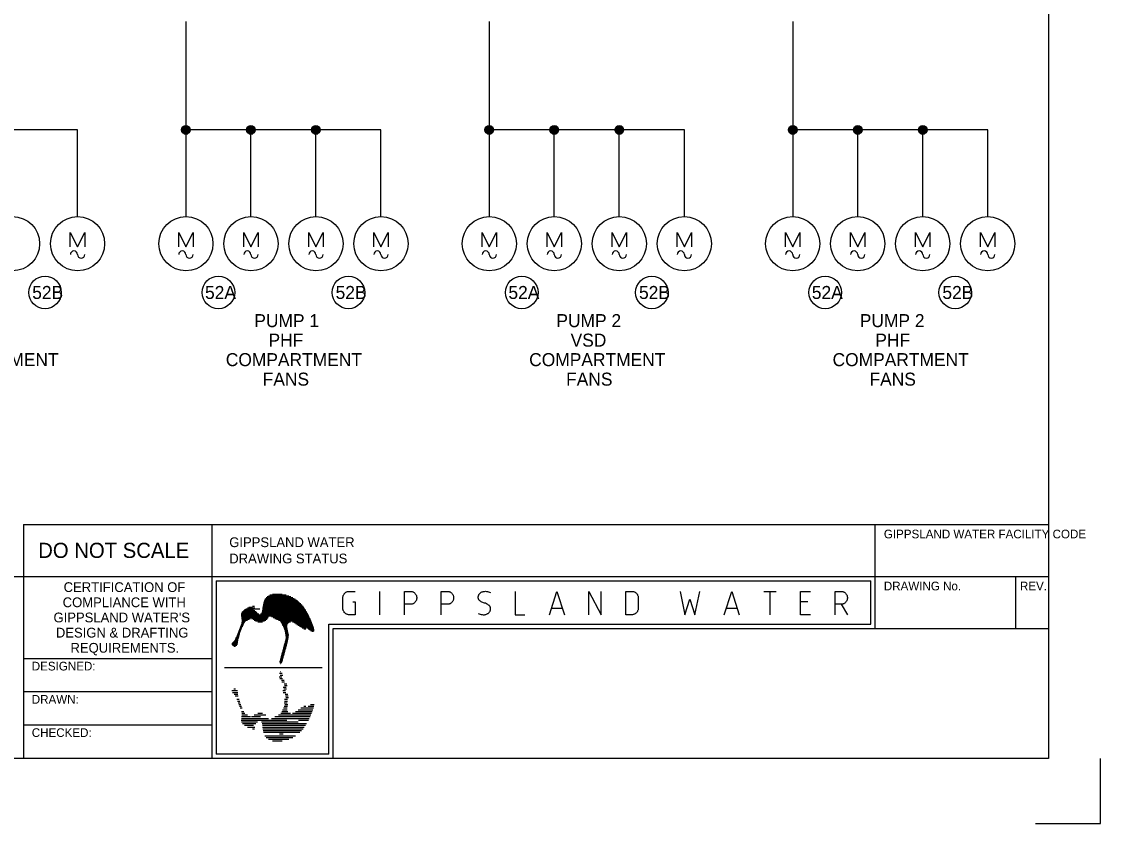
# Model space of a CAD drawing. Extents: x 0 to 841, y 0 to 594.
# Drawn here: x 592.1 to 841, y 0 to 185 of the extents above; entities that cross this region are included whole.
import ezdxf

# ---------------------------------------------------------------- set-up
doc = ezdxf.new("R2010")
doc.units = 0
for name, color, linetype in [('A1BORDER', 7, 'Continuous'), ('Level 1', 7, 'Continuous'), ('Level 10', 7, 'Continuous')]:
    doc.layers.add(name, color=color, linetype=linetype)

msp = doc.modelspace()

# ---------------------------------------------------------------- linework, layer by layer
at = {"layer": 'A1BORDER'}
for p, q in [((829, 581), (829, 15)), ((592.5, 69), (592.5, 15)), ((592.5, 69), (829, 69)), ((636, 69), (636, 15)), ((789, 45), (789, 69)), ((28, 57), (829, 57)), ((637, 56), (788, 56)), ((637, 56), (637, 16)), ((788, 46), (788, 56)), ((821.5, 45), (821.5, 57)), ((648.74, 52.32), (654.24, 52.32)), ((649.02, 52.52), (653.76, 52.52)), ((649.39, 52.72), (653.15, 52.72)), ((650.01, 52.92), (652.2, 52.92)), ((644.54, 49.92), (645.36, 49.92)), ((645.37, 50.12), (645.86, 50.12)), ((647.75, 49.92), (657.17, 49.92)), ((647.78, 50.12), (657.02, 50.12)), ((647.81, 50.32), (656.86, 50.32)), ((647.85, 50.52), (656.69, 50.52)), ((647.88, 50.72), (656.5, 50.72)), ((647.91, 50.92), (656.3, 50.92)), ((647.96, 51.12), (656.08, 51.12)), ((648.03, 51.32), (655.85, 51.32)), ((648.12, 51.52), (655.59, 51.52)), ((648.23, 51.72), (655.31, 51.72)), ((648.37, 51.92), (655, 51.92)), ((648.53, 52.12), (654.64, 52.12)), ((642.73, 48.12), (658.25, 48.12)), ((642.74, 47.92), (658.35, 47.92)), ((642.75, 48.32), (646.79, 48.32)), ((642.79, 47.72), (649.08, 47.72)), ((642.81, 48.52), (646.55, 48.52)), ((642.83, 47.52), (648.95, 47.52)), ((642.85, 47.31), (644.88, 47.31)), ((642.9, 48.72), (646.37, 48.72)), ((643.04, 48.92), (646.16, 48.92)), ((643.26, 49.12), (645.9, 49.12)), ((643.54, 49.32), (645.57, 49.32)), ((643.85, 49.52), (647.09, 49.52)), ((644.18, 49.72), (645.89, 49.72)), ((645.14, 47.31), (648.83, 47.31)), ((647.19, 48.32), (658.14, 48.32)), ((647.42, 48.52), (658.03, 48.52)), ((647.54, 48.72), (657.92, 48.72)), ((647.61, 48.92), (657.8, 48.92)), ((647.63, 49.12), (657.68, 49.12)), ((647.66, 49.32), (657.57, 49.32)), ((647.69, 49.52), (657.44, 49.52)), ((647.71, 49.72), (657.31, 49.72)), ((649.72, 47.72), (658.45, 47.72)), ((650.12, 47.52), (658.55, 47.52)), ((650.48, 47.31), (658.64, 47.31)), ((642.35, 44.92), (642.83, 44.92)), ((642.43, 45.12), (642.9, 45.12)), ((642.5, 45.32), (643, 45.32)), ((642.57, 45.52), (643.1, 45.52)), ((642.65, 45.72), (643.2, 45.72)), ((642.72, 45.92), (643.3, 45.92)), ((642.79, 46.12), (643.4, 46.12)), ((642.84, 46.32), (643.5, 46.32)), ((642.87, 47.12), (644.57, 47.12)), ((642.87, 46.52), (643.6, 46.52)), ((642.88, 46.92), (644.23, 46.92)), ((642.88, 46.72), (643.83, 46.72)), ((645.49, 47.12), (648.67, 47.12)), ((645.76, 46.92), (648.42, 46.92)), ((646.05, 46.72), (648.11, 46.72)), ((646.62, 46.52), (647.67, 46.52)), ((650.87, 47.12), (658.73, 47.12)), ((651.36, 46.92), (658.82, 46.92)), ((651.76, 46.72), (658.9, 46.72)), ((651.88, 46.52), (654.15, 46.52)), ((651.99, 46.32), (653.71, 46.32)), ((652.1, 46.12), (653.52, 46.12)), ((652.2, 45.92), (653.4, 45.92)), ((652.31, 45.72), (653.33, 45.72)), ((652.41, 45.52), (653.31, 45.52)), ((652.5, 45.32), (653.34, 45.32)), ((652.6, 45.12), (653.38, 45.12)), ((652.69, 44.92), (653.41, 44.92)), ((654.57, 46.52), (658.99, 46.52)), ((655, 46.32), (659.07, 46.32)), ((655.31, 46.12), (659.14, 46.12)), ((655.62, 45.92), (659.22, 45.92)), ((655.93, 45.72), (659.29, 45.72)), ((656.24, 45.52), (659.35, 45.52)), ((656.55, 45.32), (659.42, 45.32)), ((656.86, 45.12), (657.74, 45.12)), ((657.17, 44.92), (657.68, 44.92)), ((657.91, 45.12), (659.48, 45.12)), ((658.19, 44.92), (659.54, 44.92)), ((663, 46), (788, 46)), ((663, 16), (663, 46)), ((664, 45), (829, 45)), ((664, 15), (664, 45)), ((641.37, 42.52), (642.09, 42.52)), ((641.46, 42.72), (642.15, 42.72)), ((641.55, 42.92), (642.2, 42.92)), ((641.64, 43.12), (642.25, 43.12)), ((641.73, 43.32), (642.3, 43.32)), ((641.82, 43.51), (642.35, 43.51)), ((641.91, 43.72), (642.41, 43.72)), ((641.99, 43.92), (642.48, 43.92)), ((642.06, 44.12), (642.55, 44.12)), ((642.13, 44.32), (642.62, 44.32)), ((642.21, 44.52), (642.69, 44.52)), ((642.28, 44.72), (642.76, 44.72)), ((652.78, 44.72), (653.44, 44.72)), ((652.83, 44.52), (653.48, 44.52)), ((652.86, 44.32), (653.53, 44.32)), ((652.89, 44.12), (653.57, 44.12)), ((652.91, 43.92), (653.62, 43.92)), ((652.94, 43.72), (653.67, 43.72)), ((652.97, 43.51), (653.71, 43.51)), ((652.99, 42.52), (653.57, 42.52)), ((653, 43.32), (653.69, 43.32)), ((653.02, 43.12), (653.67, 43.12)), ((653.03, 42.72), (653.61, 42.72)), ((653.05, 42.92), (653.64, 42.92)), ((657.51, 44.72), (657.54, 44.72)), ((658.47, 44.72), (659.59, 44.72)), ((658.75, 44.52), (659.58, 44.52)), ((659.02, 44.32), (659.47, 44.32)), ((640.62, 41.32), (641.88, 41.32)), ((640.63, 41.52), (641.93, 41.52)), ((640.72, 41.12), (641.73, 41.12)), ((640.73, 41.72), (641.95, 41.72)), ((640.9, 41.92), (641.97, 41.92)), ((641.03, 40.92), (641.43, 40.92)), ((641.1, 42.12), (642, 42.12)), ((641.25, 42.31), (642.04, 42.31)), ((652.3, 39.92), (652.93, 39.92)), ((652.36, 40.12), (652.99, 40.12)), ((652.41, 40.32), (653.04, 40.32)), ((652.47, 40.52), (653.1, 40.52)), ((652.52, 40.72), (653.15, 40.72)), ((652.57, 40.92), (653.2, 40.92)), ((652.63, 41.12), (653.26, 41.12)), ((652.68, 41.32), (653.31, 41.32)), ((652.74, 41.52), (653.37, 41.52)), ((652.79, 41.72), (653.41, 41.72)), ((652.85, 41.92), (653.45, 41.92)), ((652.9, 42.12), (653.49, 42.12)), ((652.95, 42.31), (653.53, 42.31)), ((636, 38), (592.5, 38)), ((651.65, 37.52), (652.28, 37.52)), ((651.71, 37.72), (652.34, 37.72)), ((651.76, 37.92), (652.39, 37.92)), ((651.82, 38.12), (652.44, 38.12)), ((651.87, 38.32), (652.5, 38.32)), ((651.92, 38.52), (652.55, 38.52)), ((651.98, 38.72), (652.61, 38.72)), ((652.03, 38.92), (652.66, 38.92)), ((652.09, 39.12), (652.72, 39.12)), ((652.14, 39.32), (652.77, 39.32)), ((652.2, 39.52), (652.82, 39.52)), ((652.25, 39.72), (652.88, 39.72)), ((638.93, 35.98), (661.47, 35.98)), ((651.63, 37.32), (652.23, 37.32)), ((651.64, 37.12), (652.17, 37.12)), ((651.79, 36.92), (651.9, 36.92)), ((651.79, 35.04), (651.9, 35.04)), ((651.54, 33.84), (652.17, 33.84)), ((651.63, 34.64), (652.23, 34.64)), ((651.65, 33.44), (652.28, 33.44)), ((651.71, 34.24), (652.34, 34.24)), ((652.03, 33.04), (652.66, 33.04)), ((652.14, 32.64), (652.77, 32.64)), ((636, 30.34), (592.5, 30.34)), ((640.62, 30.64), (641.88, 30.64)), ((640.73, 30.24), (641.95, 30.24)), ((641.03, 31.04), (641.43, 31.04)), ((652.34, 30.64), (652.97, 30.64)), ((652.45, 30.24), (653.07, 30.24)), ((652.47, 31.44), (653.1, 31.44)), ((652.57, 31.04), (653.2, 31.04)), ((652.66, 32.24), (653.29, 32.24)), ((652.77, 31.84), (653.4, 31.84)), ((641.1, 29.84), (642, 29.84)), ((641.37, 29.44), (642.09, 29.44)), ((641.73, 28.64), (642.3, 28.64)), ((641.91, 28.24), (642.41, 28.24)), ((642.06, 27.84), (642.55, 27.84)), ((642.21, 27.44), (642.69, 27.44)), ((652.66, 27.84), (653.35, 27.84)), ((652.72, 28.24), (653.44, 28.24)), ((652.77, 28.64), (653.46, 28.64)), ((652.83, 27.44), (653.48, 27.44)), ((652.9, 29.84), (653.49, 29.84)), ((652.99, 29.44), (653.57, 29.44)), ((653.05, 29.04), (653.64, 29.04)), ((658.75, 27.44), (659.58, 27.44)), ((642.35, 27.04), (642.83, 27.04)), ((642.5, 26.64), (643, 26.64)), ((642.79, 25.84), (643.4, 25.84)), ((642.87, 25.44), (643.6, 25.44)), ((642.88, 25.04), (644.23, 25.04)), ((645.76, 25.04), (648.42, 25.04)), ((646.62, 25.44), (647.67, 25.44)), ((651.36, 25.04), (658.82, 25.04)), ((651.88, 25.44), (654.15, 25.44)), ((652.1, 25.84), (653.52, 25.84)), ((652.31, 26.24), (653.33, 26.24)), ((652.5, 26.64), (653.34, 26.64)), ((652.69, 27.04), (653.41, 27.04)), ((654.57, 25.44), (658.99, 25.44)), ((655.31, 25.84), (659.14, 25.84)), ((655.93, 26.24), (659.29, 26.24)), ((656.55, 26.64), (659.42, 26.64)), ((657.17, 27.04), (657.68, 27.04)), ((658.19, 27.04), (659.54, 27.04)), ((636, 22.67), (592.5, 22.67)), ((642.73, 23.84), (653.27, 23.84)), ((642.79, 24.24), (649.08, 24.24)), ((642.81, 23.44), (646.55, 23.44)), ((642.85, 24.65), (644.88, 24.65)), ((643.04, 23.04), (646.16, 23.04)), ((643.54, 22.64), (645.57, 22.64)), ((645.14, 24.65), (647.18, 24.65)), ((647.42, 23.44), (655.89, 23.44)), ((647.61, 23.04), (657.8, 23.04)), ((647.66, 22.64), (657.57, 22.64)), ((649.72, 24.24), (658.45, 24.24)), ((650.48, 24.65), (658.64, 24.65)), ((655.94, 23.84), (658.25, 23.84)), ((644.18, 22.24), (645.89, 22.24)), ((645.37, 21.84), (645.86, 21.84)), ((647.71, 22.24), (657.31, 22.24)), ((647.78, 21.84), (657.02, 21.84)), ((647.85, 21.44), (656.69, 21.44)), ((647.91, 21.04), (656.3, 21.04)), ((648.23, 20.24), (655.31, 20.24)), ((651.57, 20.64), (652.44, 20.64)), ((648.53, 19.84), (654.64, 19.84)), ((649.02, 19.44), (653.76, 19.44)), ((650.01, 19.04), (652.2, 19.04)), ((829, 15), (28, 15)), ((663, 16), (637, 16)), ((829, 15), (829, 15)), ((841, 0), (841, 15)), ((826, 0), (841, 0))]:
    msp.add_line(p, q, dxfattribs=at)
for points in [[(668.49, 51.15), (669.06, 51.15), (669.06, 48.16), (667.64, 48.16), (667.51, 48.16), (667.39, 48.18), (667.28, 48.21), (667.15, 48.25), (667.04, 48.3), (666.93, 48.36), (666.82, 48.43), (666.73, 48.51), (666.64, 48.6), (666.55, 48.7), (666.48, 48.8), (666.41, 48.91), (666.35, 49.02), (666.31, 49.14), (666.27, 49.27), (666.24, 49.39), (666.22, 49.52), (666.22, 49.66), (666.22, 52.05), (666.22, 52.18), (666.24, 52.31), (666.27, 52.43), (666.31, 52.56), (666.35, 52.67), (666.41, 52.79), (666.48, 52.9), (666.55, 53), (666.64, 53.1), (666.73, 53.19), (666.82, 53.27), (666.93, 53.34), (667.04, 53.4), (667.15, 53.45), (667.28, 53.49), (667.39, 53.52), (667.51, 53.54), (667.64, 53.54), (669.06, 53.54)], [(674.74, 48.16), (674.74, 53.54)], [(680.42, 48.16), (680.42, 53.54), (681.84, 53.54), (681.96, 53.54), (682.08, 53.52), (682.2, 53.49), (682.32, 53.45), (682.43, 53.4), (682.54, 53.34), (682.65, 53.27), (682.74, 53.19), (682.84, 53.1), (682.92, 53), (682.99, 52.9), (683.06, 52.79), (683.12, 52.67), (683.17, 52.56), (683.21, 52.43), (683.23, 52.31), (683.25, 52.18), (683.26, 52.05), (683.25, 51.91), (683.23, 51.78), (683.21, 51.66), (683.17, 51.53), (683.12, 51.42), (683.06, 51.3), (682.99, 51.19), (682.92, 51.09), (682.84, 50.99), (682.74, 50.9), (682.65, 50.82), (682.54, 50.75), (682.43, 50.69), (682.32, 50.64), (682.2, 50.6), (682.08, 50.57), (681.96, 50.55), (681.84, 50.55), (680.42, 50.55)], [(688.93, 48.16), (688.93, 53.54), (690.35, 53.54), (690.47, 53.54), (690.59, 53.52), (690.71, 53.49), (690.83, 53.45), (690.94, 53.4), (691.05, 53.34), (691.16, 53.27), (691.26, 53.19), (691.35, 53.1), (691.43, 53), (691.51, 52.9), (691.57, 52.79), (691.63, 52.67), (691.68, 52.56), (691.72, 52.43), (691.75, 52.31), (691.76, 52.18), (691.77, 52.05), (691.76, 51.91), (691.75, 51.78), (691.72, 51.66), (691.68, 51.53), (691.63, 51.42), (691.57, 51.3), (691.51, 51.19), (691.43, 51.09), (691.35, 50.99), (691.26, 50.9), (691.16, 50.82), (691.05, 50.75), (690.94, 50.69), (690.83, 50.64), (690.71, 50.6), (690.59, 50.57), (690.47, 50.55), (690.35, 50.55), (688.93, 50.55)], [(697.45, 48.46), (697.67, 48.36), (697.9, 48.27), (698.12, 48.21), (698.36, 48.17), (698.6, 48.16), (698.84, 48.16), (698.87, 48.16), (699.03, 48.18), (699.18, 48.21), (699.33, 48.26), (699.48, 48.32), (699.62, 48.4), (699.72, 48.46), (699.81, 48.53), (699.9, 48.61), (699.98, 48.69), (700.05, 48.78), (700.11, 48.88), (700.17, 48.99), (700.22, 49.09), (700.25, 49.21), (700.28, 49.32), (700.29, 49.36), (700.3, 49.44), (700.3, 49.52), (700.3, 49.61), (700.29, 49.69), (700.27, 49.77), (700.25, 49.86), (700.22, 49.93), (700.18, 50.01), (700.14, 50.09), (700.09, 50.15), (700.04, 50.21), (700.01, 50.25), (699.85, 50.39), (699.69, 50.51), (699.52, 50.61), (699.34, 50.7), (699.15, 50.78), (698.95, 50.83), (698.87, 50.85), (698.68, 50.9), (698.49, 50.96), (698.3, 51.04), (698.12, 51.14), (697.96, 51.26), (697.8, 51.39), (697.73, 51.45), (697.67, 51.51), (697.62, 51.57), (697.58, 51.64), (697.53, 51.71), (697.5, 51.79), (697.47, 51.87), (697.46, 51.95), (697.44, 52.04), (697.43, 52.12), (697.43, 52.21), (697.44, 52.29), (697.45, 52.35), (697.47, 52.46), (697.51, 52.58), (697.55, 52.69), (697.61, 52.79), (697.67, 52.89), (697.74, 52.99), (697.82, 53.07), (697.9, 53.15), (697.99, 53.23), (698.02, 53.24), (698.15, 53.33), (698.3, 53.4), (698.44, 53.45), (698.6, 53.5), (698.75, 53.52), (698.87, 53.54), (699.11, 53.55), (699.35, 53.53), (699.58, 53.49), (699.82, 53.43), (700.04, 53.35), (700.27, 53.25)], [(705.96, 53.54), (705.96, 48.16), (708.23, 48.16)], [(713.91, 48.16), (715.61, 53.54), (717.32, 48.16)], [(722.99, 48.16), (722.99, 53.54), (725.83, 48.16), (725.83, 53.54)], [(731.52, 48.16), (731.52, 53.54), (732.94, 53.54), (733.06, 53.54), (733.18, 53.52), (733.3, 53.49), (733.42, 53.45), (733.53, 53.4), (733.64, 53.34), (733.75, 53.27), (733.84, 53.19), (733.94, 53.1), (734.02, 53), (734.09, 52.9), (734.16, 52.79), (734.22, 52.67), (734.27, 52.56), (734.31, 52.43), (734.33, 52.31), (734.35, 52.18), (734.36, 52.05), (734.36, 49.66), (734.35, 49.52), (734.33, 49.39), (734.31, 49.27), (734.27, 49.14), (734.22, 49.02), (734.16, 48.91), (734.09, 48.8), (734.02, 48.7), (733.94, 48.6), (733.84, 48.51), (733.75, 48.43), (733.64, 48.36), (733.53, 48.3), (733.42, 48.25), (733.3, 48.21), (733.18, 48.18), (733.06, 48.16), (732.94, 48.16), (731.52, 48.16)], [(744.01, 53.54), (745.14, 48.16), (746.28, 51.75), (747.41, 48.16), (748.55, 53.54)], [(754.22, 48.16), (755.92, 53.54), (757.63, 48.16)], [(763.31, 53.54), (766.15, 53.54)], [(764.73, 53.54), (764.73, 48.16)], [(774.09, 48.16), (771.82, 48.16), (771.82, 53.54), (774.09, 53.54)], [(779.78, 48.16), (779.78, 53.54), (781.2, 53.54), (781.32, 53.54), (781.44, 53.52), (781.56, 53.49), (781.68, 53.45), (781.79, 53.4), (781.9, 53.34), (782.01, 53.27), (782.1, 53.19), (782.2, 53.1), (782.28, 53), (782.35, 52.9), (782.42, 52.79), (782.48, 52.67), (782.53, 52.56), (782.56, 52.43), (782.59, 52.31), (782.61, 52.18), (782.61, 52.05), (782.61, 51.91), (782.59, 51.78), (782.56, 51.66), (782.53, 51.53), (782.48, 51.42), (782.42, 51.3), (782.35, 51.19), (782.28, 51.09), (782.2, 50.99), (782.1, 50.9), (782.01, 50.82), (781.9, 50.75), (781.79, 50.69), (781.68, 50.64), (781.56, 50.6), (781.44, 50.57), (781.32, 50.55), (781.2, 50.55), (779.78, 50.55)], [(773.53, 51.15), (771.82, 51.15)], [(781.2, 50.55), (782.61, 48.16)], [(714.48, 49.66), (716.75, 49.66)], [(754.79, 49.66), (757.06, 49.66)]]:
    msp.add_lwpolyline(points, dxfattribs=at)
at = {"layer": 'Level 1'}
for p, q in [((630, 185), (630, 140)), ((700, 185), (700, 140)), ((770, 185), (770, 140)), ((605, 160), (560, 160)), ((605, 140), (605, 160)), ((675, 160), (630, 160)), ((645, 140), (645, 160)), ((660, 140), (660, 160)), ((675, 140), (675, 160)), ((745, 160), (700, 160)), ((715, 140), (715, 160)), ((730, 140), (730, 160)), ((745, 140), (745, 160)), ((815, 160), (770, 160)), ((785, 140), (785, 160)), ((800, 140), (800, 160)), ((815, 140), (815, 160))]:
    msp.add_line(p, q, dxfattribs=at)
for centre in [(597.5, 122.5), (637.5, 122.5), (667.5, 122.5), (707.5, 122.5), (737.5, 122.5), (777.5, 122.5), (807.5, 122.5)]:
    msp.add_circle(centre, 3.75, dxfattribs=at)
at = {"layer": 'Level 10'}
for p, q in [((629, 160), (630.99, 160)), ((629.05, 160.3), (630.95, 160.3)), ((629.05, 159.7), (630.95, 159.7)), ((629.2, 160.6), (630.8, 160.6)), ((629.2, 159.4), (630.8, 159.4)), ((629.56, 160.9), (630.44, 160.9)), ((630, 161), (630, 161)), ((644, 160), (645.99, 160)), ((644.05, 160.3), (645.95, 160.3)), ((644.05, 159.7), (645.95, 159.7)), ((644.2, 160.6), (645.8, 160.6)), ((644.2, 159.4), (645.8, 159.4)), ((644.56, 160.9), (645.44, 160.9)), ((645, 161), (645, 161)), ((659, 160), (660.99, 160)), ((659.05, 160.3), (660.95, 160.3)), ((659.05, 159.7), (660.95, 159.7)), ((659.2, 160.6), (660.8, 160.6)), ((659.2, 159.4), (660.8, 159.4)), ((659.56, 160.9), (660.44, 160.9)), ((660, 161), (660, 161)), ((699, 160), (700.99, 160)), ((699.05, 160.3), (700.95, 160.3)), ((699.05, 159.7), (700.95, 159.7)), ((699.2, 160.6), (700.8, 160.6)), ((699.2, 159.4), (700.8, 159.4)), ((699.56, 160.9), (700.44, 160.9)), ((700, 161), (700, 161)), ((714, 160), (715.99, 160)), ((714.05, 160.3), (715.95, 160.3)), ((714.05, 159.7), (715.95, 159.7)), ((714.2, 160.6), (715.8, 160.6)), ((714.2, 159.4), (715.8, 159.4)), ((714.56, 160.9), (715.44, 160.9)), ((715, 161), (715, 161)), ((729, 160), (730.99, 160)), ((729.05, 160.3), (730.95, 160.3)), ((729.05, 159.7), (730.95, 159.7)), ((729.2, 160.6), (730.8, 160.6)), ((729.2, 159.4), (730.8, 159.4)), ((729.56, 160.9), (730.44, 160.9)), ((730, 161), (730, 161)), ((769, 160), (770.99, 160)), ((769.05, 160.3), (770.95, 160.3)), ((769.05, 159.7), (770.95, 159.7)), ((769.2, 160.6), (770.8, 160.6)), ((769.2, 159.4), (770.8, 159.4)), ((769.56, 160.9), (770.44, 160.9)), ((770, 161), (770, 161)), ((784, 160), (785.99, 160)), ((784.05, 160.3), (785.95, 160.3)), ((784.05, 159.7), (785.95, 159.7)), ((784.2, 160.6), (785.8, 160.6)), ((784.2, 159.4), (785.8, 159.4)), ((784.56, 160.9), (785.44, 160.9)), ((785, 161), (785, 161)), ((799, 160), (800.99, 160)), ((799.05, 160.3), (800.95, 160.3)), ((799.05, 159.7), (800.95, 159.7)), ((799.2, 160.6), (800.8, 160.6)), ((799.2, 159.4), (800.8, 159.4)), ((799.56, 160.9), (800.44, 160.9)), ((800, 161), (800, 161)), ((629.56, 159.1), (630.44, 159.1)), ((644.56, 159.1), (645.44, 159.1)), ((659.56, 159.1), (660.44, 159.1)), ((699.56, 159.1), (700.44, 159.1)), ((714.56, 159.1), (715.44, 159.1)), ((729.56, 159.1), (730.44, 159.1)), ((769.56, 159.1), (770.44, 159.1)), ((784.56, 159.1), (785.44, 159.1)), ((799.56, 159.1), (800.44, 159.1)), ((603.33, 136.33), (605, 133)), ((603.33, 133), (603.33, 136.33)), ((605, 133), (606.67, 136.33)), ((606.67, 136.33), (606.67, 133)), ((628.33, 136.33), (630, 133)), ((628.33, 133), (628.33, 136.33)), ((630, 133), (631.67, 136.33)), ((631.67, 136.33), (631.67, 133)), ((643.33, 136.33), (645, 133)), ((643.33, 133), (643.33, 136.33)), ((645, 133), (646.67, 136.33)), ((646.67, 136.33), (646.67, 133)), ((658.33, 136.33), (660, 133)), ((658.33, 133), (658.33, 136.33)), ((660, 133), (661.67, 136.33)), ((661.67, 136.33), (661.67, 133)), ((673.33, 136.33), (675, 133)), ((673.33, 133), (673.33, 136.33)), ((675, 133), (676.67, 136.33)), ((676.67, 136.33), (676.67, 133)), ((698.33, 136.33), (700, 133)), ((698.33, 133), (698.33, 136.33)), ((700, 133), (701.67, 136.33)), ((701.67, 136.33), (701.67, 133)), ((713.33, 136.33), (715, 133)), ((713.33, 133), (713.33, 136.33)), ((715, 133), (716.67, 136.33)), ((716.67, 136.33), (716.67, 133)), ((728.33, 136.33), (730, 133)), ((728.33, 133), (728.33, 136.33)), ((730, 133), (731.67, 136.33)), ((731.67, 136.33), (731.67, 133)), ((743.33, 136.33), (745, 133)), ((743.33, 133), (743.33, 136.33)), ((745, 133), (746.67, 136.33)), ((746.67, 136.33), (746.67, 133)), ((768.33, 136.33), (770, 133)), ((768.33, 133), (768.33, 136.33)), ((770, 133), (771.67, 136.33)), ((771.67, 136.33), (771.67, 133)), ((783.33, 136.33), (785, 133)), ((783.33, 133), (783.33, 136.33)), ((785, 133), (786.67, 136.33)), ((786.67, 136.33), (786.67, 133)), ((798.33, 136.33), (800, 133)), ((798.33, 133), (798.33, 136.33)), ((800, 133), (801.67, 136.33)), ((801.67, 136.33), (801.67, 133)), ((813.33, 136.33), (815, 133)), ((813.33, 133), (813.33, 136.33)), ((815, 133), (816.67, 136.33)), ((816.67, 136.33), (816.67, 133))]:
    msp.add_line(p, q, dxfattribs=at)
for centre, radius in [((630, 160), 1), ((645, 160), 1), ((660, 160), 1), ((700, 160), 1), ((715, 160), 1), ((730, 160), 1), ((770, 160), 1), ((785, 160), 1), ((800, 160), 1), ((590, 133.75), 6.25), ((605, 133.75), 6.25), ((630, 133.75), 6.25), ((645, 133.75), 6.25), ((660, 133.75), 6.25), ((675, 133.75), 6.25), ((700, 133.75), 6.25), ((715, 133.75), 6.25), ((730, 133.75), 6.25), ((745, 133.75), 6.25), ((770, 133.75), 6.25), ((785, 133.75), 6.25), ((800, 133.75), 6.25), ((815, 133.75), 6.25)]:
    msp.add_circle(centre, radius, dxfattribs=at)
for centre, start, end in [((604.17, 131.25), 0, 180), ((629.17, 131.25), 0, 180), ((644.17, 131.25), 0, 180), ((659.17, 131.25), 0, 180), ((674.17, 131.25), 0, 180), ((699.17, 131.25), 0, 180), ((714.17, 131.25), 0, 180), ((729.17, 131.25), 0, 180), ((744.17, 131.25), 0, 180), ((769.17, 131.25), 0, 180), ((784.17, 131.25), 0, 180), ((799.17, 131.25), 0, 180), ((814.17, 131.25), 0, 180), ((605.83, 131.25), 180, 0), ((630.83, 131.25), 180, 0), ((645.83, 131.25), 180, 0), ((660.83, 131.25), 180, 0), ((675.83, 131.25), 180, 0), ((700.83, 131.25), 180, 0), ((715.83, 131.25), 180, 0), ((730.83, 131.25), 180, 0), ((745.83, 131.25), 180, 0), ((770.83, 131.25), 180, 0), ((785.83, 131.25), 180, 0), ((800.83, 131.25), 180, 0), ((815.83, 131.25), 180, 0)]:
    msp.add_arc(centre, 0.83, start, end, dxfattribs=at)

# ---------------------------------------------------------------- texts
at = {"layer": 'A1BORDER'}
for s, height, p in [('GIPPSLAND WATER FACILITY CODE', 2, (791.03, 65.77)), ('DO NOT SCALE', 3.5, (595.92, 61.25)), ('GIPPSLAND WATER', 2.25, (640, 63.75)), ('DRAWING STATUS', 2.25, (640, 60)), ('CERTIFICATION OF', 2.25, (601.79, 53.39)), ('DRAWING No.', 2, (791.03, 53.77)), ('REV.', 2, (822.43, 53.77)), ('COMPLIANCE WITH', 2.25, (601.57, 49.89)), ("GIPPSLAND WATER'S", 2.25, (599.45, 46.39)), ('DESIGN & DRAFTING', 2.25, (600, 42.89)), ('REQUIREMENTS.', 2.25, (603.37, 39.39)), ('DESIGNED:', 2, (594.44, 35.29)), ('DRAWN:', 2, (594.44, 27.62)), ('CHECKED:', 2, (594.44, 19.95))]:
    msp.add_text(s, height=height, dxfattribs=at).set_placement(p)
at = {"layer": 'Level 1'}
for s, p in [('52B', (594.54, 121)), ('52A', (634.41, 121)), ('52B', (664.54, 121)), ('52A', (704.41, 121)), ('52B', (734.54, 121)), ('52A', (774.41, 121)), ('52B', (804.54, 121)), ('PUMP 1', (645.78, 114.5)), ('PUMP 2', (715.48, 114.5)), ('PUMP 2', (785.48, 114.5)), ('PHF', (649.06, 110)), ('VSD', (718.76, 110)), ('PHF', (789.06, 110)), ('COMPARTMENT', (569.2, 105.5)), ('COMPARTMENT', (639.2, 105.5)), ('COMPARTMENT', (709.2, 105.5)), ('COMPARTMENT', (779.2, 105.5)), ('FANS', (647.72, 101)), ('FANS', (717.72, 101)), ('FANS', (787.72, 101))]:
    msp.add_text(s, height=3, dxfattribs=at).set_placement(p)

doc.saveas('drawing.dxf')
